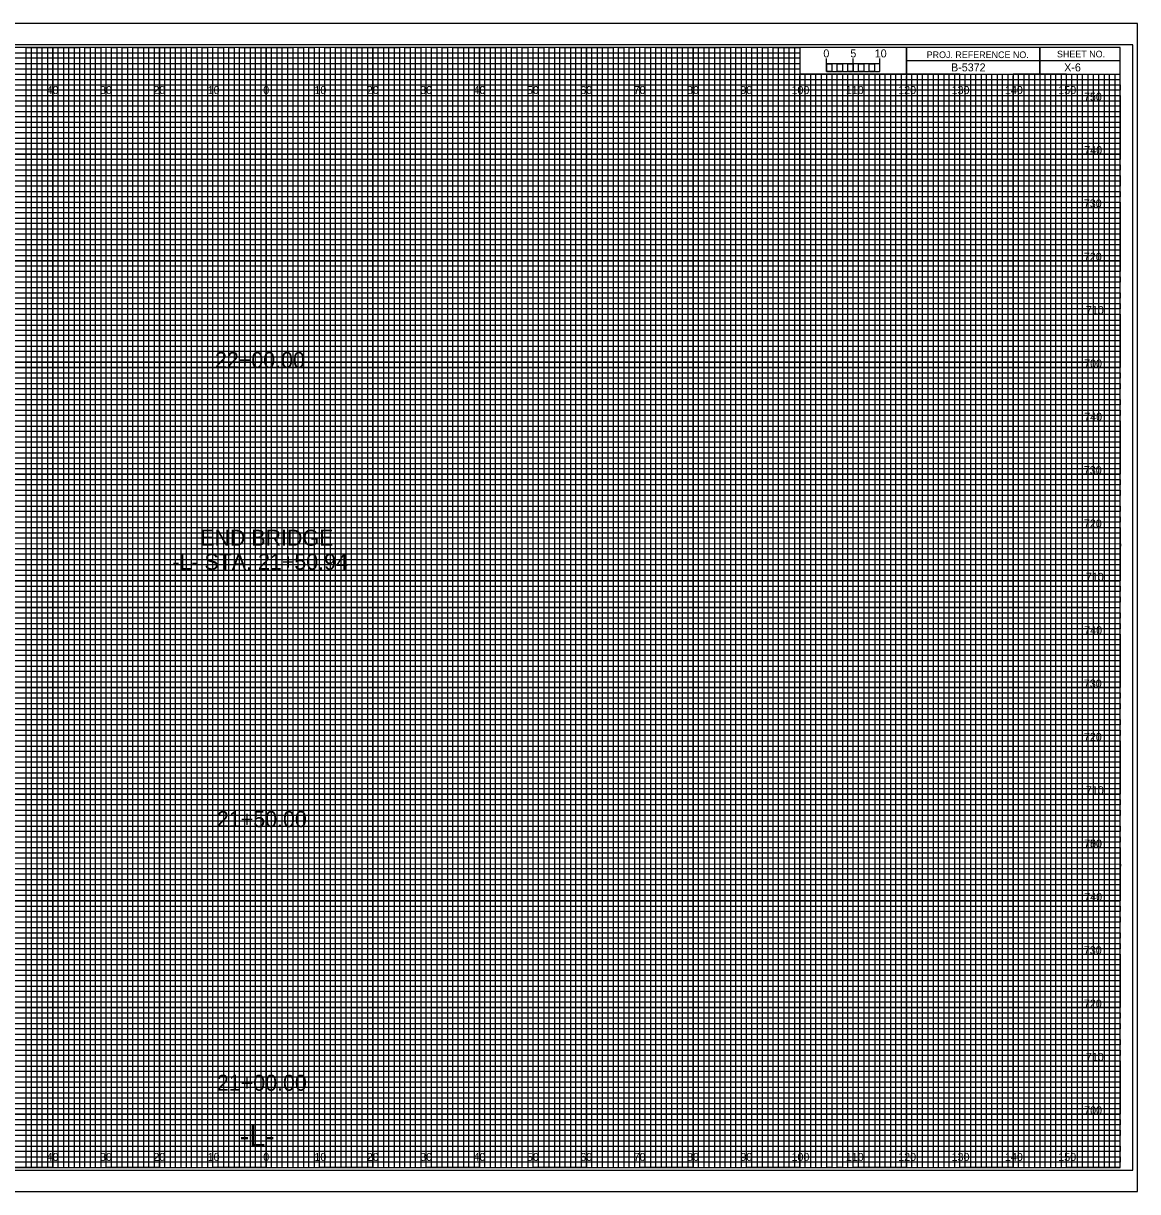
# Model space of a CAD drawing. Extents: x -98 to 717, y -10 to 1974.
# Drawn here: x 114.5 to 323.3, y 1095.5 to 1314.5 of the extents above; entities that cross this region are included whole.
import ezdxf

# ---------------------------------------------------------------- set-up
doc = ezdxf.new("R2010")
doc.units = 0
for name, color, linetype in [('Default', 7, 'Continuous'), ('Exist XS Center Line Elevation Label', 7, 'Continuous'), ('Prop CMT Conc Surface', 7, 'Continuous'), ('Prop CMT Concrete Structures', 7, 'Continuous'), ('Prop CMT Pvmt Course 1', 7, 'Continuous'), ('Prop CMT Pvmt Course 1 CG', 7, 'Continuous'), ('Prop CMT Pvmt Course 2', 7, 'Continuous'), ('Prop CMT Pvmt Course 3', 7, 'Continuous'), ('Prop CMT Pvmt Surface', 7, 'Continuous'), ('Prop CMT Pvmt Surface Shoulder', 7, 'Continuous'), ('Prop CMT Shld Paved Course 1', 7, 'Continuous'), ('Prop CMT Shld Paved Course 2', 7, 'Continuous'), ('Prop CMT Shld Paved Course 3', 7, 'Continuous'), ('Prop CMT Slope Grass', 7, 'Continuous'), ('Prop CMT Subgrade Earthwork', 7, 'Continuous'), ('Prop XS Ditch Standard Text', 7, 'Continuous'), ('Prop XS Earthwork Shape', 7, 'Continuous'), ('Prop XS Elevation Labels', 7, 'Continuous'), ('Typical Curb CELL', 7, 'Continuous')]:
    doc.layers.add(name, color=color, linetype=linetype)

msp = doc.modelspace()

# ---------------------------------------------------------------- linework, layer by layer
at = {"layer": 'Default'}
msp.add_lwpolyline([(-13.4, 1095.5), (323.3, 1095.5), (323.3, 1314.5), (-13.4, 1314.5)], close=True, dxfattribs=at)
at = {"layer": 'Exist XS Center Line Elevation Label'}
for p, q in [((0, 1309), (260, 1309)), ((260, 1307.98), (0, 1307.98)), ((260, 1309), (260, 1307.98)), ((0, 1307), (260, 1307)), ((260, 1305.89), (0, 1305.89)), ((260, 1307), (260, 1305.89)), ((0, 1304), (320, 1304))]:
    msp.add_line(p, q, dxfattribs=at)
for points in [[(0, 1303), (270, 1303), (320, 1303), (320, 1302), (0, 1302)], [(0, 1301), (320, 1301), (320, 1299), (0, 1299)], [(0, 1298), (320, 1298), (320, 1297), (0, 1296.98)], [(0, 1296), (320, 1296), (320, 1294), (0, 1294)], [(0, 1293), (320, 1293), (320, 1292), (0, 1292)], [(0, 1291), (320, 1291), (320, 1289), (0, 1289)], [(0, 1288), (320, 1288), (320, 1287), (0, 1287)], [(0, 1286), (320, 1286), (320, 1284), (0, 1284)], [(0, 1283), (320, 1283), (320, 1282), (0, 1282)], [(0, 1281), (320, 1281), (320, 1279), (0, 1279)], [(0, 1278), (320, 1278), (320, 1277), (0, 1277)], [(0, 1276), (320, 1276), (320, 1273.95), (320, 1273), (320, 1272), (0, 1272)], [(0, 1274), (320, 1274), (320, 1273), (0, 1273)], [(0, 1271), (320, 1271), (320, 1269), (0, 1269.03)], [(0, 1269.03), (320, 1269), (320, 1268), (0, 1268)], [(0, 1267), (320, 1267), (320, 1266), (0, 1266)], [(0, 1264), (320, 1264), (320, 1263), (0, 1263)], [(0, 1262), (320, 1262), (320, 1261), (0, 1261)], [(-0.07, 1258.89), (320, 1258.89), (320, 1257.88), (-0.07, 1257.88)], [(0, 1257), (320, 1257), (320, 1256), (0, 1256)], [(0, 1254), (320, 1254), (320, 1253), (0, 1253)], [(0, 1252), (320, 1252), (320, 1251), (0, 1251)], [(0, 1249), (320, 1249), (320, 1248), (0, 1248)], [(0, 1247), (320, 1247), (320, 1246), (0, 1246)], [(0, 1244), (320, 1244), (320, 1243), (0, 1243)], [(0, 1242), (320, 1242), (320, 1241), (0, 1241)], [(0, 1239), (320, 1239), (319.99, 1237.98), (0, 1238)], [(0, 1237), (320, 1237), (320, 1236), (0, 1236)], [(0, 1234), (320, 1234), (320, 1233), (0, 1233)], [(0, 1232), (320, 1232), (320, 1231), (0, 1231)], [(0, 1229), (320, 1229), (320, 1228), (0, 1228)], [(0, 1227), (320, 1227), (320, 1226), (0, 1226)], [(0, 1224), (320, 1224), (320, 1223), (0, 1223)], [(0, 1222), (320, 1222), (320, 1221), (0, 1221)], [(0, 1219), (320, 1219), (320, 1218), (0, 1218)], [(0, 1216.99), (320.07, 1216.91), (320, 1216), (0, 1216)], [(0, 1214), (320, 1214), (320, 1213), (0, 1213)], [(0, 1212), (320, 1212), (320, 1211), (0, 1211)], [(0, 1209), (320, 1209), (320, 1208), (0, 1208)], [(0, 1207), (320, 1207), (320, 1206), (0, 1206)], [(0, 1204), (320, 1204), (320, 1203), (0, 1203)], [(0, 1202), (320, 1202), (320, 1201), (0, 1201)], [(0, 1199), (320, 1199), (320, 1198), (0, 1198)], [(0, 1197), (320, 1197), (320, 1196), (0, 1196)], [(0, 1194), (320, 1194), (320, 1193), (0, 1193)], [(0, 1192), (320, 1192), (320, 1191), (0, 1191)], [(0, 1189), (320, 1189), (320, 1188), (0, 1188)], [(0, 1187), (320, 1187), (320, 1186), (0, 1186)], [(0, 1184), (320, 1184), (320, 1183), (0, 1183)], [(0, 1182), (320, 1182), (320, 1181), (0, 1181)], [(0, 1179), (320, 1179), (319.99, 1177.98), (0, 1178)], [(0, 1177), (320, 1177), (320, 1176), (0, 1176)], [(0, 1174), (320, 1174), (320, 1173), (0, 1173)], [(0, 1172), (320, 1172), (320, 1171), (0, 1171)], [(0, 1169), (320, 1169), (320, 1168), (0, 1168)], [(0, 1167), (320, 1167), (320, 1166), (0, 1166)], [(0, 1164), (320, 1164), (320, 1163), (0, 1163)], [(0, 1162), (320, 1162), (320, 1161), (0, 1161)], [(0, 1159), (320, 1159), (320, 1158), (0, 1158)], [(0, 1156.99), (320.07, 1156.91), (320, 1156), (0, 1156)], [(0, 1154), (320, 1154), (320, 1153), (0, 1153)], [(0, 1152), (320, 1152), (320, 1151), (0, 1151)], [(0, 1149), (320, 1149), (320, 1148), (0, 1148)], [(0, 1147), (320, 1147), (320, 1146), (0, 1146)], [(0, 1144), (320, 1144), (320, 1143), (0, 1143)], [(0, 1142), (320, 1142), (320, 1141), (0, 1141)], [(0, 1139), (320, 1139), (320, 1138), (0, 1138)], [(0, 1137), (320, 1137), (320, 1136), (0, 1136)], [(0, 1134), (320, 1134), (320, 1133), (0, 1133)], [(0, 1132), (320, 1132), (320, 1131), (0, 1131)], [(0, 1129), (320, 1129), (320, 1128), (0, 1128)], [(0, 1127), (320, 1127), (320, 1126), (0, 1126)], [(0, 1124), (320, 1124), (320, 1123), (0, 1123)], [(0, 1122), (320, 1122), (320, 1121), (0, 1121)], [(0, 1119), (320, 1119), (320, 1118), (0, 1118)], [(0, 1117), (320, 1117), (320, 1116), (0, 1116)], [(0, 1114), (320, 1114), (320, 1113), (0, 1113)], [(0, 1112), (320, 1112), (320, 1111), (0, 1111)], [(0, 1109), (320, 1109), (320, 1108), (0, 1108)], [(0, 1107), (320, 1107), (320, 1106), (0, 1106)], [(0, 1104), (320, 1104), (320, 1103), (0, 1103)], [(0, 1102), (320, 1102), (320, 1101), (0, 1101)]]:
    msp.add_lwpolyline(points, dxfattribs=at)
at = {"layer": 'Prop CMT Conc Surface'}
for p, q in [((305, 1310), (305, 1305)), ((305, 1305), (305, 1310)), ((280, 1307.5), (280, 1305)), ((320, 1307.49), (280, 1307.49)), ((280, 1305), (320, 1305))]:
    msp.add_line(p, q, dxfattribs=at)
for points in [[(320, 1310), (0, 1310), (0, 1100), (320, 1100)], [(280, 1310), (260, 1310), (260, 1305.03), (280, 1305.03)], [(320, 1310), (280, 1310), (280, 1305), (320, 1305)]]:
    msp.add_lwpolyline(points, close=True, dxfattribs=at)
at = {"layer": 'Prop CMT Concrete Structures'}
for p, q in [((120, 1100), (120, 1310)), ((130, 1100), (130, 1310)), ((140, 1100), (140, 1310)), ((150, 1100), (150, 1310)), ((160, 1100), (160, 1310)), ((170, 1100), (170, 1310)), ((180, 1100), (180, 1310)), ((190, 1100), (190, 1310)), ((200, 1100), (200, 1310)), ((210, 1100), (210, 1310)), ((220, 1100), (220, 1310)), ((230, 1100), (230, 1310)), ((240, 1100), (240, 1310)), ((250, 1100), (250, 1310)), ((260, 1100), (260, 1304.69)), ((270, 1100), (270, 1304.69)), ((280, 1100), (280, 1304.69)), ((290, 1100), (290, 1304.69)), ((300, 1100), (300, 1304.69)), ((310, 1100), (310, 1304.69)), ((0, 1300), (320, 1300)), ((0, 1290), (320, 1290)), ((0, 1280), (320, 1280)), ((0, 1270), (320, 1270)), ((0, 1260), (320, 1260)), ((0, 1250), (320, 1250)), ((0, 1240), (320, 1240)), ((0, 1230), (320, 1230)), ((0, 1220), (320, 1220)), ((0, 1210), (320, 1210)), ((0, 1200), (320, 1200)), ((0, 1190), (320, 1190)), ((0, 1180), (320, 1180)), ((0, 1170), (320, 1170)), ((0, 1160), (320, 1160)), ((0, 1150), (320, 1150)), ((0, 1140), (320, 1140)), ((0, 1130), (320, 1130)), ((0, 1120), (320, 1120)), ((0, 1110), (320, 1110))]:
    msp.add_line(p, q, dxfattribs=at)
at = {"layer": 'Prop CMT Pvmt Course 2'}
msp.add_lwpolyline([(-13.4, 1095.5), (323.3, 1095.5), (323.3, 1314.5), (-13.4, 1314.5)], close=True, dxfattribs=at)
at = {"layer": 'Prop CMT Pvmt Course 3'}
msp.add_lwpolyline([(-10.8, 1099.5), (322.4, 1099.5), (322.4, 1310.5), (-10.8, 1310.5)], close=True, dxfattribs=at)
at = {"layer": 'Prop CMT Pvmt Surface'}
for p, q in [((323.3, 1314.5), (-13.4, 1314.5)), ((-13.4, 1095.5), (323.3, 1095.5))]:
    msp.add_line(p, q, dxfattribs=at)
at = {"layer": 'Prop CMT Slope Grass'}
for p, q in [((265, 1305.49), (265, 1307.9)), ((265, 1306.9), (265, 1307.9)), ((270, 1305.49), (270, 1307.9)), ((275, 1305.49), (275, 1307.9)), ((275, 1306.9), (275, 1307.9))]:
    msp.add_line(p, q, dxfattribs=at)
for points in [[(275, 1306.9), (265, 1306.9), (265, 1305.49), (275, 1305.49)], [(265, 1306.9), (266, 1306.9), (266, 1305.49), (265, 1305.49)], [(267, 1306.9), (268, 1306.9), (268, 1305.49), (267, 1305.49)], [(269, 1306.9), (270, 1306.9), (270, 1305.49), (269, 1305.49)], [(271, 1306.9), (272, 1306.9), (272, 1305.49), (271, 1305.49)], [(273, 1306.9), (274, 1306.9), (274, 1305.49), (273, 1305.49)]]:
    msp.add_lwpolyline(points, close=True, dxfattribs=at)
at = {"layer": 'Prop CMT Subgrade Earthwork'}
for p, q in [((267, 1305), (266.01, 1305)), ((266.01, 1305), (266.01, 1100)), ((267, 1100), (267, 1305)), ((269, 1305), (268, 1305)), ((268, 1305), (268, 1100)), ((269, 1100), (269, 1305)), ((266.01, 1100), (265, 1100)), ((268, 1100), (267, 1100))]:
    msp.add_line(p, q, dxfattribs=at)
for points in [[(115, 1100), (116, 1100), (116, 1310), (117, 1310), (117, 1100)], [(117, 1100), (118, 1100), (118, 1310), (119, 1310), (119, 1100)], [(120, 1100), (121, 1100), (121, 1310), (122, 1310), (122, 1100)], [(122, 1100), (123, 1100), (123, 1310), (124, 1310), (124, 1100)], [(125, 1100), (126, 1100), (126, 1310), (127, 1310), (127, 1100)], [(127, 1100), (128, 1100), (128, 1310), (129, 1310), (129, 1100)], [(130, 1100), (131, 1100), (131, 1310), (132, 1310), (132, 1100)], [(132, 1100), (133, 1100), (133, 1310), (134, 1310), (134, 1100)], [(135, 1100), (136, 1100), (136, 1310), (137, 1310), (137, 1100)], [(137, 1100), (138, 1100), (138, 1310), (139, 1310), (139, 1100)], [(140, 1100), (141, 1100), (141, 1310), (142, 1310), (142, 1100)], [(142, 1100), (143, 1100), (143, 1310), (144, 1310), (144, 1100)], [(145, 1100), (146, 1100), (146, 1310), (147, 1310), (147, 1100)], [(147, 1100), (148, 1100), (148, 1310), (149, 1310), (149, 1100)], [(150, 1100), (151, 1100), (151, 1310), (152, 1310), (152, 1100)], [(152, 1100), (153, 1100), (153, 1310), (154, 1310), (154, 1100)], [(155, 1100), (156, 1100), (156, 1310), (157, 1310), (157, 1100)], [(157, 1100), (158, 1100), (158, 1310), (159, 1310), (159, 1100)], [(160, 1100), (161, 1100), (161, 1310), (162, 1310), (162, 1100)], [(162, 1100), (163, 1100), (163, 1310), (164, 1310), (164, 1100)], [(165, 1100), (166, 1100), (166, 1310), (167, 1310), (167, 1100)], [(167, 1100), (168, 1100), (168, 1310), (169, 1310), (169, 1100)], [(170, 1100), (171, 1100), (171, 1310), (172, 1310), (172, 1100)], [(172, 1100), (173, 1100), (173, 1310), (174, 1310), (174, 1100)], [(175, 1100), (176, 1100), (176, 1310), (177, 1310), (177, 1100)], [(177, 1100), (178, 1100), (178, 1310), (179, 1310), (179, 1100)], [(180, 1100), (181, 1100), (181, 1310), (182, 1310), (182, 1100)], [(182, 1100), (183, 1100), (183, 1310), (184, 1310), (184, 1100)], [(185, 1100), (186, 1100), (186, 1310), (187, 1310), (187, 1100)], [(187, 1100), (188, 1100), (188, 1310), (189, 1310), (189, 1100)], [(190, 1100), (191, 1100), (191, 1310), (192, 1310), (192, 1100)], [(192, 1100), (193, 1100), (193, 1310), (194, 1310), (194, 1100)], [(195, 1100), (196, 1100), (196, 1310), (197, 1310), (197, 1100)], [(197, 1100), (198, 1100), (198, 1310), (199, 1310), (199, 1100)], [(200, 1100), (201, 1100), (201, 1310), (202, 1310), (202, 1100)], [(202, 1100), (203, 1100), (203, 1310), (204, 1310), (204, 1100)], [(205, 1100), (206, 1100), (206, 1310), (207, 1310), (207, 1100)], [(207, 1100), (208, 1100), (208, 1310), (209, 1310), (209, 1100)], [(210, 1100), (211, 1100), (211, 1310), (212, 1310), (212, 1100)], [(212, 1100), (213, 1100), (213, 1310), (214, 1310), (214, 1100)], [(215, 1100), (216, 1100), (216, 1310), (217, 1310), (217, 1100)], [(217, 1100), (218, 1100), (218, 1310), (219, 1310), (219, 1100)], [(220, 1100), (221, 1100), (221, 1310), (222, 1310), (222, 1100)], [(222, 1100), (223, 1100), (223, 1310), (224, 1310), (224, 1100)], [(225, 1100), (226, 1100), (226, 1310), (227, 1310), (227, 1100)], [(227, 1100), (228, 1100), (228, 1310), (229, 1310), (229, 1100)], [(230, 1100), (231, 1100), (231, 1310), (232, 1310), (232, 1100)], [(232, 1100), (233, 1100), (233, 1310), (234, 1310), (234, 1100)], [(235, 1100), (236, 1100), (236, 1310), (237, 1310), (237, 1100)], [(237, 1100), (238, 1100), (238, 1310), (239, 1310), (239, 1100)], [(240, 1100), (241, 1100), (241, 1310), (242, 1310), (242, 1100)], [(242, 1100), (243, 1100), (243, 1310), (244, 1310), (244, 1100)], [(245, 1100), (246, 1100), (246, 1310), (247, 1310), (247, 1100)], [(247, 1100), (248, 1100), (248, 1310), (249, 1310), (249, 1100)], [(250, 1100), (251, 1100), (251, 1310), (252, 1310), (252, 1100)], [(252, 1100), (253, 1100), (253, 1310), (254, 1310), (254, 1100)], [(255, 1100), (256, 1100), (256, 1310), (257, 1310), (257, 1100)], [(257, 1100), (258, 1100), (258, 1310), (259, 1310), (259, 1100)], [(260, 1100), (261, 1100), (261, 1305), (262.02, 1305), (262.02, 1100)], [(262, 1100), (263, 1100), (263, 1305), (263.99, 1305), (263.99, 1100)], [(270, 1100), (270.98, 1100), (270.98, 1305), (272, 1305), (272, 1100)], [(272, 1100), (273, 1100), (273, 1305), (274.05, 1305), (274.05, 1100)], [(275, 1100), (276, 1100), (276, 1305), (277, 1305), (277, 1100)], [(277, 1100), (278, 1100), (278, 1305), (279, 1305), (279, 1100)], [(280, 1100), (281, 1100), (281, 1305), (282, 1305), (282, 1100)], [(282, 1100), (283, 1100), (283, 1305), (284, 1305), (284, 1100)], [(285, 1100), (286, 1100), (286, 1305), (287, 1305), (287, 1100)], [(287, 1100), (288, 1100), (288, 1305), (289, 1305), (289, 1100)], [(290, 1100), (291, 1100), (291, 1305), (292, 1305), (292, 1100)], [(292, 1100), (293, 1100), (293, 1305), (294, 1305), (294, 1100)], [(295, 1100), (296, 1100), (296, 1305), (297, 1305), (297, 1100)], [(297, 1100), (298, 1100), (298, 1305), (299, 1305), (299, 1100)], [(300, 1100), (301, 1100), (301, 1305), (302, 1305), (302, 1100)], [(302, 1100), (303, 1100), (303, 1305), (304, 1305), (304, 1100)], [(305, 1100), (306, 1100), (306, 1305), (307, 1305), (307, 1100)], [(307, 1100), (308, 1100), (308, 1305), (309, 1305), (309, 1100)], [(310, 1100), (311, 1100), (311, 1305), (312, 1305), (312, 1100)], [(312, 1100), (313, 1100), (313, 1305), (314, 1305), (314, 1100)], [(315, 1100), (316, 1100), (316, 1305), (317, 1305), (317, 1100)], [(317, 1100), (318, 1100), (318, 1305), (319, 1305), (319, 1100)]]:
    msp.add_lwpolyline(points, dxfattribs=at)
at = {"layer": 'Prop XS Ditch Standard Text'}
msp.add_lwpolyline([(1, 1251), (314, 1251), (314, 1205), (1, 1205)], close=True, dxfattribs=at)
at = {"layer": 'Prop XS Elevation Labels'}
for p, q in [((130, 1310), (120, 1310)), ((120, 1310), (120, 1100)), ((130, 1100), (130, 1310)), ((150, 1310), (140, 1310)), ((140, 1310), (140, 1100)), ((150, 1100), (150, 1310)), ((170, 1310), (160, 1310)), ((160, 1310), (160, 1100)), ((170, 1100), (170, 1310)), ((190, 1310), (180, 1310)), ((180, 1310), (180, 1100)), ((190, 1100), (190, 1310)), ((210, 1310), (200, 1310)), ((200, 1310), (200, 1100)), ((210, 1100), (210, 1310)), ((230, 1310), (220, 1310)), ((220, 1310), (220, 1100)), ((230, 1100), (230, 1310)), ((250, 1310), (240, 1310)), ((240, 1310), (240, 1100)), ((250, 1100), (250, 1310)), ((260, 1310), (260, 1100)), ((270, 1100), (270, 1305)), ((290, 1305), (280, 1305)), ((280, 1305), (280, 1100)), ((290, 1100), (290, 1305)), ((310, 1305), (300, 1305)), ((300, 1305), (300, 1100)), ((310, 1100), (310, 1305)), ((120, 1100), (110, 1100)), ((140, 1100), (130, 1100)), ((160, 1100), (150, 1100)), ((180, 1100), (170, 1100)), ((200, 1100), (190, 1100)), ((220, 1100), (210, 1100)), ((240, 1100), (230, 1100)), ((260, 1100), (250, 1100)), ((280, 1100), (270, 1100)), ((300, 1100), (290, 1100)), ((320, 1100), (310, 1100)), ((320, 1100), (320, 1100))]:
    msp.add_line(p, q, dxfattribs=at)
for points in [[(0, 1300), (320, 1300), (320, 1290), (0, 1290)], [(0, 1280), (320, 1280), (320, 1270), (0, 1270)], [(0, 1260), (320, 1260), (320, 1250), (0, 1250)], [(0, 1240), (320, 1240), (320, 1230), (0, 1230)], [(0, 1220), (320, 1220), (320, 1210), (0, 1210)], [(0, 1200), (320, 1200), (320, 1190), (0, 1190)], [(0, 1180), (320, 1180), (320, 1170), (0, 1170)], [(0, 1160), (320, 1160), (320, 1150), (0, 1150)], [(0, 1140), (320, 1140), (320, 1130), (0, 1130)], [(0, 1120), (320, 1120), (320, 1110), (0, 1110)]]:
    msp.add_lwpolyline(points, dxfattribs=at)
at = {"layer": 'Typical Curb CELL'}
for points in [[(105, 1100), (115, 1100), (115, 1310), (125, 1310), (125, 1100), (135, 1100), (135, 1310), (145, 1310), (145, 1100), (155, 1100), (155, 1310), (165, 1310), (165, 1100), (175, 1100), (175, 1310), (185, 1310), (185, 1100), (195, 1100), (195, 1310), (205, 1310), (205, 1100), (215, 1100), (215, 1310), (225, 1310), (225, 1100), (235, 1100), (235, 1310), (245, 1310), (245, 1100), (255, 1100), (255, 1310), (259.93, 1310), (260, 1310), (260, 1305), (264.99, 1305), (264.99, 1100), (275, 1100), (275, 1305), (285, 1305), (285, 1100), (295, 1100), (295, 1305), (305, 1305), (305, 1100), (315, 1100), (315, 1305)], [(0, 1305), (275, 1305)], [(0, 1285), (320, 1285), (320, 1295), (0, 1295)], [(0, 1265), (320, 1265), (320, 1275), (0, 1275)], [(0, 1245), (320, 1245), (320, 1255), (0, 1255)], [(0, 1225), (320, 1225), (320, 1235), (0, 1235)], [(0, 1205), (320, 1205), (320, 1215), (0, 1215)], [(0, 1185), (320, 1185), (320, 1195), (0, 1195)], [(0, 1165), (320, 1165), (320, 1175), (0, 1175)], [(0, 1145), (320, 1145), (320, 1155), (0, 1155)], [(0, 1125), (320, 1125), (320, 1135), (0, 1135)], [(0, 1105), (320, 1105), (320, 1115), (0, 1115)]]:
    msp.add_lwpolyline(points, dxfattribs=at)

# ---------------------------------------------------------------- texts
at = {"layer": 'Prop CMT Conc Surface'}
for s, p in [('PROJ. REFERENCE NO.', (283.77, 1307.99)), ('SHEET NO.', (308.19, 1308.12))]:
    msp.add_text(s, height=1.25, dxfattribs=at).set_placement(p)
at = {"layer": 'Prop CMT Pvmt Course 1'}
for s, p in [('22+00.00', (150.41, 1249.89)), ('END BRIDGE', (147.63, 1216.58)), ('-L- STA. 21+50.94', (142.42, 1212.08)), ('21+50.00', (150.77, 1163.84)), ('21+00.00', (150.77, 1114.41))]:
    msp.add_text(s, height=3, dxfattribs=at).set_placement(p)
at = {"layer": 'Prop CMT Pvmt Course 1 CG'}
for s, p in [('750', (313.25, 1300)), ('740', (313.3, 1290)), ('730', (313.22, 1280)), ('720', (313.23, 1270)), ('710', (313.61, 1260)), ('700', (313.28, 1250)), ('740', (313.3, 1240)), ('730', (313.22, 1230)), ('720', (313.23, 1220)), ('710', (313.61, 1210)), ('740', (313.3, 1200)), ('730', (313.22, 1190)), ('720', (313.23, 1180)), ('710', (313.61, 1170)), ('750', (313.25, 1160)), ('700', (313.28, 1160)), ('740', (313.3, 1150)), ('730', (313.22, 1140)), ('720', (313.23, 1130)), ('710', (313.61, 1120)), ('700', (313.28, 1110))]:
    msp.add_text(s, height=1.5, dxfattribs=at).set_placement(p)
at = {"layer": 'Prop CMT Pvmt Surface Shoulder'}
for s, p in [('5', (269.47, 1308.12)), ('10', (274.04, 1308.12))]:
    msp.add_text(s, height=1.5, dxfattribs=at).set_placement(p)
at = {"layer": 'Prop CMT Shld Paved Course 1'}
msp.add_text('X-6', height=1.5, dxfattribs=at).set_placement((309.54, 1305.5))
at = {"layer": 'Prop CMT Shld Paved Course 2'}
msp.add_text('B-5372', height=1.5, dxfattribs=at).set_placement((288.34, 1305.5))
at = {"layer": 'Prop CMT Shld Paved Course 3'}
msp.add_text('-L-', height=4, dxfattribs=at).set_placement((155.06, 1104))
at = {"layer": 'Prop CMT Slope Grass'}
msp.add_text('0', height=1.5, dxfattribs=at).set_placement((264.41, 1308.12))
at = {"layer": 'Prop XS Earthwork Shape'}
for s, p in [('40', (118.86, 1301.25)), ('30', (128.86, 1301.25)), ('20', (138.86, 1301.25)), ('10', (149.04, 1301.25)), ('0', (159.45, 1301.25)), ('0', (159.45, 1301.25)), ('10', (169.04, 1301.25)), ('20', (178.86, 1301.25)), ('30', (188.86, 1301.25)), ('40', (198.86, 1301.25)), ('50', (208.86, 1301.25)), ('60', (218.86, 1301.25)), ('70', (228.86, 1301.25)), ('80', (238.86, 1301.25)), ('90', (248.86, 1301.25)), ('100', (258.44, 1301.25)), ('110', (268.62, 1301.25)), ('120', (278.44, 1301.25)), ('130', (288.44, 1301.25)), ('140', (298.44, 1301.25)), ('150', (308.44, 1301.25)), ('40', (118.86, 1101.25)), ('30', (128.86, 1101.25)), ('20', (138.86, 1101.25)), ('10', (149.04, 1101.25)), ('0', (159.45, 1101.25)), ('0', (159.45, 1101.25)), ('10', (169.04, 1101.25)), ('20', (178.86, 1101.25)), ('30', (188.86, 1101.25)), ('40', (198.86, 1101.25)), ('50', (208.86, 1101.25)), ('60', (218.86, 1101.25)), ('70', (228.86, 1101.25)), ('80', (238.86, 1101.25)), ('90', (248.86, 1101.25)), ('100', (258.44, 1101.25)), ('110', (268.62, 1101.25)), ('120', (278.44, 1101.25)), ('130', (288.44, 1101.25)), ('140', (298.44, 1101.25)), ('150', (308.44, 1101.25))]:
    msp.add_text(s, height=1.5, dxfattribs=at).set_placement(p)

doc.saveas('drawing.dxf')
